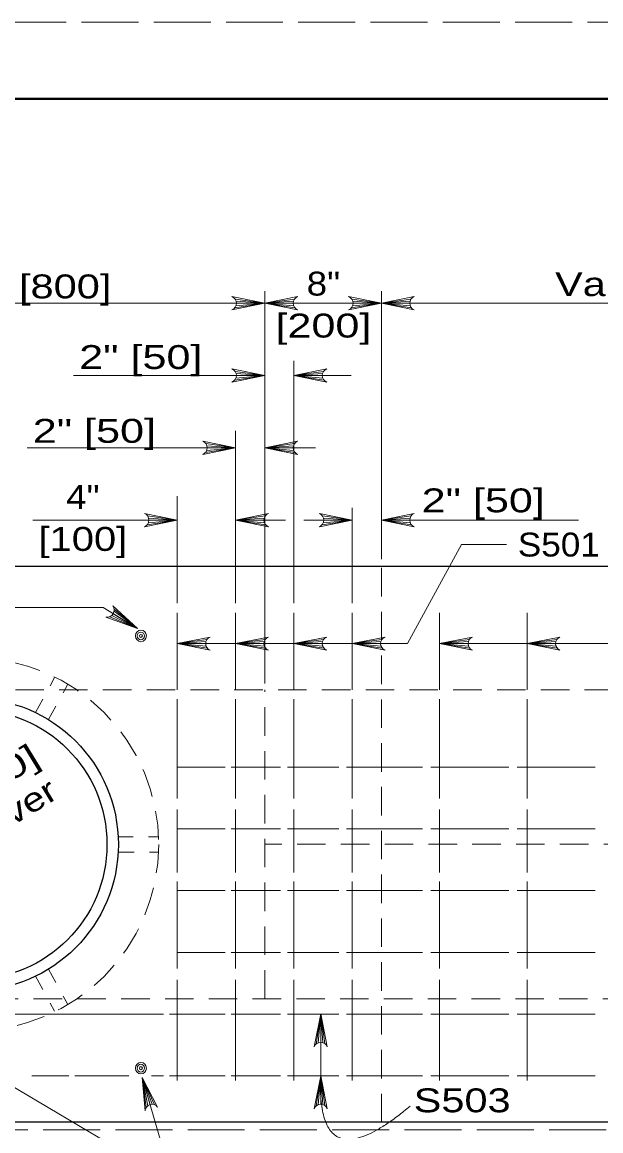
# Model space of a CAD drawing. Extents: x 339.1 to 373.1, y 1412.7 to 1456.7.
# Drawn here: x 347.29 to 351.06, y 1449.51 to 1456.75 of the extents above; entities that cross this region are included whole.
import ezdxf
from ezdxf.enums import TextEntityAlignment as Align

# ---------------------------------------------------------------- set-up
doc = ezdxf.new("R2010")
doc.units = 0
doc.header["$LTSCALE"] = 0.062
for name, pattern in [('DOTTED', [1.5, 0.3, -1.2]), ('LONG_DASHED', [7.5, 6, -1.5]), ('MEDIUM_DASHED', [4.5, 3, -1.5])]:
    doc.linetypes.add(name, pattern=pattern)
doc.layers.add('1', color=7, linetype='Continuous', lineweight=13)

msp = doc.modelspace()

# ---------------------------------------------------------------- linework, layer by layer
at = {"layer": '1', "lineweight": 25}
for p, q in [((341.0605, 1456.2455), (372.5605, 1456.2455)), ((360.97275, 1449.56467), (343.61608, 1449.56467))]:
    msp.add_line(p, q, dxfattribs=at)
at = {"layer": '1'}
for p, q in [((348.67575, 1454.938), (348.86958, 1454.91083)), ((348.86958, 1452.42925), (348.86958, 1454.9895)), ((349.0635, 1454.938), (348.86958, 1454.91083)), ((349.43725, 1454.938), (349.63108, 1454.91083)), ((349.63108, 1453.23942), (349.63108, 1454.9895)), ((349.825, 1454.938), (349.63108, 1454.91083)), ((347.44108, 1454.91083), (345.82367, 1454.91083)), ((348.86958, 1454.91083), (347.44108, 1454.91083)), ((348.67342, 1454.88092), (348.86958, 1454.91083)), ((348.68083, 1454.89342), (348.86958, 1454.91083)), ((348.68225, 1454.92458), (348.86958, 1454.91083)), ((348.68425, 1454.91083), (348.86958, 1454.91083)), ((349.05692, 1454.92458), (348.86958, 1454.91083)), ((349.07567, 1454.91083), (348.86958, 1454.91083)), ((349.05492, 1454.91083), (348.86958, 1454.91083)), ((349.05833, 1454.89342), (348.86958, 1454.91083)), ((349.06583, 1454.88092), (348.86958, 1454.91083)), ((349.43492, 1454.88092), (349.63108, 1454.91083)), ((349.44233, 1454.89342), (349.63108, 1454.91083)), ((349.44375, 1454.92458), (349.63108, 1454.91083)), ((349.44575, 1454.91083), (349.63108, 1454.91083)), ((349.81842, 1454.92458), (349.63108, 1454.91083)), ((349.81642, 1454.91083), (349.63108, 1454.91083)), ((349.81983, 1454.89342), (349.63108, 1454.91083)), ((349.82725, 1454.88092), (349.63108, 1454.91083)), ((349.06, 1452.95308), (349.06, 1454.5345)), ((347.62067, 1454.43883), (348.86958, 1454.43883)), ((348.67342, 1454.40892), (348.86958, 1454.43883)), ((348.67575, 1454.466), (348.86958, 1454.43883)), ((348.68083, 1454.42142), (348.86958, 1454.43883)), ((348.68225, 1454.45258), (348.86958, 1454.43883)), ((348.68425, 1454.43883), (348.86958, 1454.43883)), ((349.24733, 1454.45258), (349.06, 1454.43883)), ((349.24533, 1454.43883), (349.06, 1454.43883)), ((349.24875, 1454.42142), (349.06, 1454.43883)), ((349.25617, 1454.40892), (349.06, 1454.43883)), ((348.67925, 1452.95308), (348.67925, 1454.07825)), ((348.48533, 1453.994), (348.67925, 1453.96683)), ((349.0635, 1453.994), (348.86958, 1453.96683)), ((347.31742, 1453.96683), (348.67925, 1453.96683)), ((348.48308, 1453.93692), (348.67925, 1453.96683)), ((348.4905, 1453.94942), (348.67925, 1453.96683)), ((348.49192, 1453.98058), (348.67925, 1453.96683)), ((348.49392, 1453.96683), (348.67925, 1453.96683)), ((349.05692, 1453.98058), (348.86958, 1453.96683)), ((349.05492, 1453.96683), (348.86958, 1453.96683)), ((349.05833, 1453.94942), (348.86958, 1453.96683)), ((349.06583, 1453.93692), (348.86958, 1453.96683)), ((348.86958, 1453.96683), (349.20008, 1453.96683)), ((348.2985, 1452.95308), (348.2985, 1453.65225)), ((349.44075, 1452.95308), (349.44075, 1453.57458)), ((347.35533, 1453.49483), (348.2985, 1453.49483)), ((348.10233, 1453.46492), (348.2985, 1453.49483)), ((348.10458, 1453.522), (348.2985, 1453.49483)), ((348.10975, 1453.47742), (348.2985, 1453.49483)), ((348.11117, 1453.50858), (348.2985, 1453.49483)), ((348.11317, 1453.49483), (348.2985, 1453.49483)), ((348.87317, 1453.522), (348.67925, 1453.49483)), ((348.86658, 1453.50858), (348.67925, 1453.49483)), ((348.67925, 1453.49483), (349.00417, 1453.49483)), ((348.86458, 1453.49483), (348.67925, 1453.49483)), ((348.868, 1453.47742), (348.67925, 1453.49483)), ((348.87542, 1453.46492), (348.67925, 1453.49483)), ((349.12425, 1453.49483), (349.44075, 1453.49483)), ((349.24458, 1453.46492), (349.44075, 1453.49483)), ((349.24683, 1453.522), (349.44075, 1453.49483)), ((349.252, 1453.47742), (349.44075, 1453.49483)), ((349.25342, 1453.50858), (349.44075, 1453.49483)), ((349.25542, 1453.49483), (349.44075, 1453.49483)), ((349.825, 1453.522), (349.63108, 1453.49483)), ((349.81842, 1453.50858), (349.63108, 1453.49483)), ((349.63108, 1453.49483), (350.91842, 1453.49483)), ((349.81642, 1453.49483), (349.63108, 1453.49483)), ((349.81983, 1453.47742), (349.63108, 1453.49483)), ((349.82725, 1453.46492), (349.63108, 1453.49483)), ((349.80225, 1452.68867), (350.15467, 1453.33492)), ((350.15467, 1453.33492), (350.44733, 1453.33492)), ((347.8135, 1452.92358), (345.18583, 1452.92358)), ((348.0375, 1452.78658), (347.8135, 1452.92358)), ((347.88575, 1452.9145), (348.0375, 1452.78658)), ((347.85792, 1452.86458), (348.0375, 1452.78658)), ((347.8705, 1452.87267), (348.0375, 1452.78658)), ((347.87942, 1452.88333), (348.0375, 1452.78658)), ((347.88558, 1452.89992), (348.0375, 1452.78658)), ((348.2985, 1452.38633), (348.2985, 1452.89025)), ((348.67925, 1452.38633), (348.67925, 1452.89025)), ((349.06, 1452.38633), (349.06, 1452.89025)), ((349.44075, 1452.38633), (349.44075, 1452.89025)), ((350.01183, 1452.38633), (350.01183, 1452.89025)), ((350.583, 1452.38633), (350.583, 1452.89025)), ((348.49242, 1452.71575), (348.2985, 1452.68867)), ((348.48583, 1452.70233), (348.2985, 1452.68867)), ((348.48383, 1452.68867), (348.2985, 1452.68867)), ((348.48725, 1452.67125), (348.2985, 1452.68867)), ((348.49467, 1452.65867), (348.2985, 1452.68867)), ((348.87317, 1452.71575), (348.67925, 1452.68867)), ((348.86658, 1452.70233), (348.67925, 1452.68867)), ((348.86458, 1452.68867), (348.67925, 1452.68867)), ((348.868, 1452.67125), (348.67925, 1452.68867)), ((348.87542, 1452.65867), (348.67925, 1452.68867)), ((349.25392, 1452.71575), (349.06, 1452.68867)), ((349.24733, 1452.70233), (349.06, 1452.68867)), ((349.24533, 1452.68867), (349.06, 1452.68867)), ((349.24875, 1452.67125), (349.06, 1452.68867)), ((349.25617, 1452.65867), (349.06, 1452.68867)), ((349.63467, 1452.71575), (349.44075, 1452.68867)), ((349.62808, 1452.70233), (349.44075, 1452.68867)), ((349.62608, 1452.68867), (349.44075, 1452.68867)), ((349.6295, 1452.67125), (349.44075, 1452.68867)), ((349.63692, 1452.65867), (349.44075, 1452.68867)), ((350.20575, 1452.71575), (350.01183, 1452.68867)), ((350.19917, 1452.70233), (350.01183, 1452.68867)), ((350.19717, 1452.68867), (350.01183, 1452.68867)), ((350.20058, 1452.67125), (350.01183, 1452.68867)), ((350.208, 1452.65867), (350.01183, 1452.68867)), ((350.77683, 1452.71575), (350.583, 1452.68867)), ((350.77033, 1452.70233), (350.583, 1452.68867)), ((350.76833, 1452.68867), (350.583, 1452.68867)), ((350.77175, 1452.67125), (350.583, 1452.68867)), ((350.77917, 1452.65867), (350.583, 1452.68867)), ((348.2985, 1451.67858), (348.2985, 1452.32525)), ((348.67925, 1451.67858), (348.67925, 1452.32525)), ((349.06, 1451.67858), (349.06, 1452.32525)), ((349.44075, 1451.67858), (349.44075, 1452.32525)), ((350.01183, 1451.67858), (350.01183, 1452.32525)), ((350.583, 1451.67858), (350.583, 1452.32525)), ((348.6105, 1451.88242), (348.2985, 1451.88242)), ((348.97317, 1451.88242), (348.65092, 1451.88242)), ((349.35375, 1451.88242), (349.018, 1451.88242)), ((349.9, 1451.88242), (349.403, 1451.88242)), ((350.46417, 1451.88242), (349.95367, 1451.88242)), ((351.02825, 1451.88242), (350.51783, 1451.88242)), ((348.2985, 1451.19358), (348.2985, 1451.6055)), ((348.67925, 1451.19358), (348.67925, 1451.6055)), ((349.06, 1451.19358), (349.06, 1451.6055)), ((349.44075, 1451.19358), (349.44075, 1451.6055)), ((350.01183, 1451.19358), (350.01183, 1451.6055)), ((350.583, 1451.19358), (350.583, 1451.6055)), ((348.6105, 1451.47933), (348.2985, 1451.47933)), ((348.97317, 1451.47933), (348.65092, 1451.47933)), ((349.35375, 1451.47933), (349.018, 1451.47933)), ((349.9, 1451.47933), (349.403, 1451.47933)), ((350.46417, 1451.47933), (349.95367, 1451.47933)), ((351.02825, 1451.47933), (350.51783, 1451.47933)), ((348.2985, 1450.56767), (348.2985, 1451.13608)), ((348.67925, 1450.56767), (348.67925, 1451.13608)), ((349.06, 1450.56767), (349.06, 1451.13608)), ((349.44075, 1450.56767), (349.44075, 1451.13608)), ((350.01183, 1450.56767), (350.01183, 1451.13608)), ((350.583, 1450.56767), (350.583, 1451.13608)), ((348.6105, 1451.07625), (348.2985, 1451.07625)), ((348.97317, 1451.07625), (348.65092, 1451.07625)), ((349.35375, 1451.07625), (349.018, 1451.07625)), ((349.9, 1451.07625), (349.403, 1451.07625)), ((350.46417, 1451.07625), (349.95367, 1451.07625)), ((351.02825, 1451.07625), (350.51783, 1451.07625)), ((348.6105, 1450.67317), (348.2985, 1450.67317)), ((348.97317, 1450.67317), (348.65092, 1450.67317)), ((349.35375, 1450.67317), (349.018, 1450.67317)), ((349.9, 1450.67317), (349.403, 1450.67317)), ((350.46417, 1450.67317), (349.95367, 1450.67317)), ((351.02825, 1450.67317), (350.51783, 1450.67317)), ((348.2985, 1449.8375), (348.2985, 1450.49467)), ((348.67925, 1449.8375), (348.67925, 1450.49467)), ((349.06, 1449.8375), (349.06, 1450.49467)), ((349.44075, 1449.8375), (349.44075, 1450.49467)), ((350.01183, 1449.8375), (350.01183, 1450.49467)), ((350.583, 1449.8375), (350.583, 1450.49467)), ((347.58933, 1450.26933), (347.03867, 1450.26933)), ((348.2075, 1450.27008), (347.58508, 1450.27008)), ((348.6105, 1450.27008), (348.24775, 1450.27008)), ((348.97317, 1450.27008), (348.65092, 1450.27008)), ((349.35375, 1450.27008), (349.018, 1450.27008)), ((349.20508, 1450.07467), (349.235, 1450.27083)), ((349.21758, 1450.08208), (349.235, 1450.27083)), ((349.235, 1450.0855), (349.235, 1450.27083)), ((349.24875, 1450.0835), (349.235, 1450.27083)), ((349.26217, 1450.077), (349.235, 1450.27083)), ((349.9, 1450.27008), (349.403, 1450.27008)), ((350.46417, 1450.27008), (349.95367, 1450.27008)), ((351.02825, 1450.27008), (350.51783, 1450.27008)), ((347.0465, 1449.903), (348.2655, 1449.18067)), ((347.58933, 1449.86692), (347.34758, 1449.86692)), ((347.98242, 1449.86692), (347.62992, 1449.86692)), ((348.2075, 1449.86692), (348.13, 1449.86692)), ((348.6105, 1449.86692), (348.24775, 1449.86692)), ((348.97317, 1449.86692), (348.65092, 1449.86692)), ((349.35375, 1449.86692), (349.018, 1449.86692)), ((349.20508, 1449.67075), (349.235, 1449.86692)), ((349.21758, 1449.67817), (349.235, 1449.86692)), ((349.235, 1449.68158), (349.235, 1449.86692)), ((349.24875, 1449.67967), (349.235, 1449.86692)), ((349.26217, 1449.67308), (349.235, 1449.86692)), ((349.9, 1449.86692), (349.403, 1449.86692)), ((350.46417, 1449.86692), (349.95367, 1449.86692)), ((351.02825, 1449.86692), (350.51783, 1449.86692)), ((348.06925, 1449.85725), (348.2655, 1449.18067)), ((348.12092, 1449.67925), (348.06925, 1449.85725)), ((348.10508, 1449.67117), (348.06925, 1449.85725)), ((348.09508, 1449.6605), (348.06925, 1449.85725)), ((348.13458, 1449.68117), (348.06925, 1449.85725)), ((348.14933, 1449.67858), (348.06925, 1449.85725))]:
    msp.add_line(p, q, dxfattribs=at)
at = {"layer": '1', "linetype": 'MEDIUM_DASHED'}
for p, q in [((349.63108, 1449.56467), (349.63108, 1453.1925)), ((357.15083, 1452.38633), (345.68083, 1452.38633)), ((348.86958, 1450.37083), (348.86958, 1452.38633)), ((353.55717, 1451.37858), (348.86958, 1451.37858)), ((354.98208, 1450.37083), (345.82367, 1450.37083))]:
    msp.add_line(p, q, dxfattribs=at)
at = {"layer": '1', "linetype": 'DOTTED'}
for p, q in [((347.37275, 1452.23842), (347.49717, 1452.4665)), ((347.4575, 1452.19233), (347.58425, 1452.42475)), ((347.90983, 1451.42825), (348.17192, 1451.42825)), ((347.91667, 1451.3275), (348.17875, 1451.3275)), ((347.37267, 1450.5175), (347.49675, 1450.29008)), ((347.45733, 1450.56375), (347.58367, 1450.33233))]:
    msp.add_line(p, q, dxfattribs=at)
at = {"layer": '1', "linetype": 'LONG_DASHED'}
msp.add_line((345.06217, 1449.51425), (357.91233, 1449.51425), dxfattribs=at)
msp.add_lwpolyline([(339.0605, 1434.7455), (373.0605, 1434.7455), (373.0605, 1456.7455), (339.0605, 1456.7455)], close=True, dxfattribs=at)
at = {"layer": '1', "lineweight": 40}
msp.add_lwpolyline([(341.0605, 1456.2455), (372.5605, 1456.2455), (372.5605, 1435.2455), (341.0605, 1435.2455)], close=True, dxfattribs=at)
at = {"layer": '1'}
for points in [[(348.65542, 1454.868), (348.86958, 1454.91083), (348.65542, 1454.95367)], [(349.08375, 1454.868), (348.86958, 1454.91083), (349.08375, 1454.95367)], [(349.41692, 1454.868), (349.63108, 1454.91083), (349.41692, 1454.95367)], [(349.84525, 1454.868), (349.63108, 1454.91083), (349.84525, 1454.95367)], [(355.63825, 1454.91083), (349.63108, 1454.91083), (349.01208, 1454.91083)], [(348.65542, 1454.396), (348.86958, 1454.43883), (348.65542, 1454.48167)], [(349.27417, 1454.396), (349.06, 1454.43883), (349.27417, 1454.48167)], [(349.25392, 1454.466), (349.06, 1454.43883), (349.43383, 1454.43883)], [(348.46508, 1453.924), (348.67925, 1453.96683), (348.46508, 1454.00967)], [(349.08375, 1453.924), (348.86958, 1453.96683), (349.08375, 1454.00967)], [(348.08433, 1453.452), (348.2985, 1453.49483), (348.08433, 1453.53767)], [(348.89342, 1453.452), (348.67925, 1453.49483), (348.89342, 1453.53767)], [(349.22658, 1453.452), (349.44075, 1453.49483), (349.22658, 1453.53767)], [(349.84525, 1453.452), (349.63108, 1453.49483), (349.84525, 1453.53767)], [(347.87708, 1452.93492), (348.0375, 1452.78658), (347.83242, 1452.86183)], [(348.51267, 1452.64583), (348.2985, 1452.68867), (348.51267, 1452.7315)], [(349.80225, 1452.68867), (349.44075, 1452.68867), (349.06, 1452.68867), (348.67925, 1452.68867), (348.2985, 1452.68867)], [(348.89342, 1452.64583), (348.67925, 1452.68867), (348.89342, 1452.7315)], [(349.27417, 1452.64583), (349.06, 1452.68867), (349.27417, 1452.7315)], [(349.65492, 1452.64583), (349.44075, 1452.68867), (349.65492, 1452.7315)], [(350.226, 1452.64583), (350.01183, 1452.68867), (350.226, 1452.7315)], [(354.00967, 1452.68867), (353.43858, 1452.68867), (352.86742, 1452.68867), (352.29633, 1452.68867), (351.72525, 1452.68867), (351.15408, 1452.68867), (350.583, 1452.68867), (350.01183, 1452.68867)], [(350.79717, 1452.64583), (350.583, 1452.68867), (350.79717, 1452.7315)], [(349.19217, 1450.05667), (349.235, 1450.27083), (349.27783, 1450.05667)], [(349.235, 1449.70017), (349.235, 1449.86692), (349.235, 1450.27083)], [(349.19217, 1449.65275), (349.235, 1449.86692), (349.27783, 1449.65275)], [(348.08775, 1449.63967), (348.06925, 1449.85725), (348.17008, 1449.6635)]]:
    msp.add_lwpolyline(points, dxfattribs=at)
at = {"layer": '1', "lineweight": 25}
msp.add_lwpolyline([(357.91233, 1449.51425), (357.91233, 1453.1925), (343.58617, 1453.1925)], dxfattribs=at)
at = {"layer": '1', "linetype": 'MEDIUM_DASHED'}
msp.add_circle((346.95836, 1451.37788), 1.21838, dxfattribs=at)
at = {"layer": '1', "lineweight": 25}
for radius in [0.95499, 0.88079]:
    msp.add_circle((346.95836, 1451.37788), radius, dxfattribs=at)
at = {"layer": '1'}
for centre, start, end in [((348.63815, 1454.91092), 292.08605, 67.91218), ((349.10108, 1454.91092), 112.08782, 247.91395), ((349.39964, 1454.91092), 292.08605, 67.91218), ((349.86257, 1454.91092), 112.08782, 247.91395), ((348.63815, 1454.43891), 292.08605, 67.91218), ((349.29145, 1454.43891), 112.08782, 247.91395), ((348.44777, 1453.96691), 292.08605, 67.91218), ((349.10108, 1453.96691), 112.08782, 247.91395), ((348.06703, 1453.49491), 292.08605, 67.91218), ((348.91071, 1453.49491), 112.08782, 247.91395), ((349.20927, 1453.49491), 292.08605, 67.91218), ((349.86257, 1453.49491), 112.08782, 247.91395), ((347.83999, 1452.90733), 260.64309, 36.46922), ((348.52996, 1452.68871), 112.08782, 247.91395), ((348.91071, 1452.68871), 112.08782, 247.91395), ((349.29145, 1452.68871), 112.08782, 247.91395), ((349.6722, 1452.68871), 112.08782, 247.91395), ((350.24332, 1452.68871), 112.08782, 247.91395), ((350.81444, 1452.68871), 112.08782, 247.91395), ((349.23508, 1450.03939), 22.08782, 157.91395), ((348.13379, 1449.63498), 38.25717, 174.0833), ((349.23508, 1449.63549), 22.08782, 157.91395)]:
    msp.add_arc(centre, 0.04623, start, end, dxfattribs=at)
for centre, major_axis in [((348.06053, 1452.73915), (0, 0.03779)), ((348.06053, 1452.7391), (0, -0.02519)), ((348.06053, 1452.73915), (0, 0.01008)), ((348.06053, 1449.91734), (0, 0.03779)), ((348.06053, 1449.91734), (0, 0.02519)), ((348.06053, 1449.91734), (0, 0.01008))]:
    msp.add_ellipse(centre, major_axis=major_axis, ratio=0.944544, dxfattribs=at)
msp.add_open_spline([(349.235, 1449.86692), (349.20283, 1449.15325), (349.81833, 1449.669)], degree=2, dxfattribs=at)

# ---------------------------------------------------------------- texts
for s, width, p in [('2\'-8" [800]', 1.3, (346.64933, 1454.9425)), ('Variable 2\'-8" [0.8 m] to 16\'-8" [5.0 m]', 1.3, (350.76533, 1454.95733)), ('2" [50]', 1.35, (347.65775, 1454.48125)), ('2" [50]', 1.35, (347.35475, 1453.99958)), ('2" [50]', 1.35, (349.89425, 1453.54567)), ('S501', 1.1, (350.52217, 1453.25725)), ('S503', 1.3, (349.84208, 1449.62917))]:
    msp.add_text(s, height=0.156, dxfattribs=dict(at, width=width)).set_placement(p)
for s, width, p in [('8"', 1.15, (349.25262, 1454.96075)), ('[200]', 1.35, (349.25271, 1454.68675)), ('4"', 1.15, (347.68171, 1453.568)), ('[100]', 1.25, (347.68162, 1453.294))]:
    msp.add_text(s, height=0.156, dxfattribs=dict(at, width=width)).set_placement(p, align=Align.CENTER)
for s, width, p in [('18" [450]', 1.4, (346.91799, 1451.60621)), ('dia. cover', 1.25, (347.04899, 1451.39186))]:
    msp.add_text(s, height=0.156, rotation=31.435, dxfattribs=dict(at, width=width)).set_placement(p, align=Align.CENTER)

doc.saveas('drawing.dxf')
